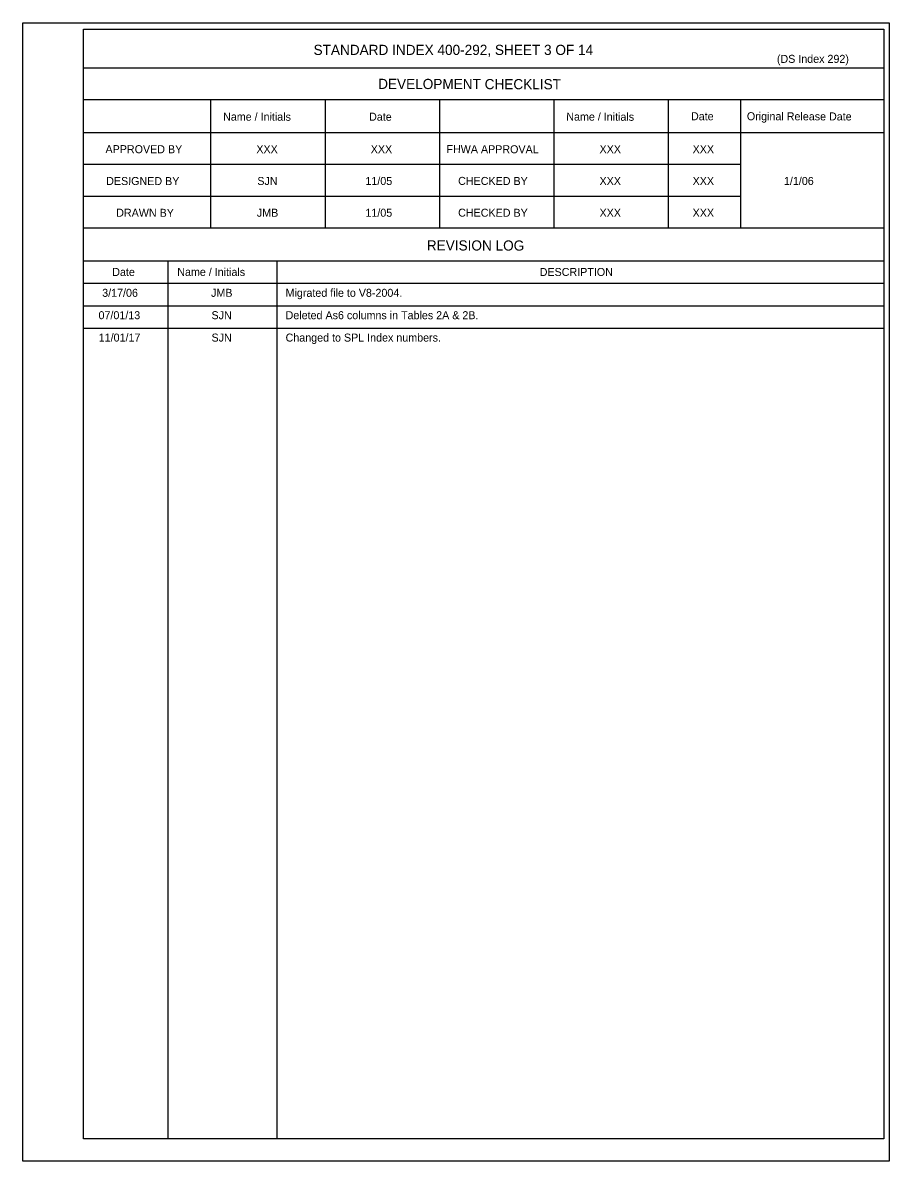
# Model space of a CAD drawing. Extents: x 10340.93 to 10343.14, y 76399.51 to 76400.59.
# Drawn here: x 10342.462 to 10343.144, y 76399.632 to 76400.528 of the extents above; entities that cross this region are included whole.
import ezdxf

# ---------------------------------------------------------------- set-up
doc = ezdxf.new("R2010")
doc.units = 0
doc.layers.add('AdhocPoint_dp', color=7, linetype='Continuous')
doc.layers.add('Border', color=7, linetype='Continuous')

msp = doc.modelspace()

# ---------------------------------------------------------------- linework, layer by layer
at = {"layer": 'AdhocPoint_dp'}
for p, q in [((10342.50988, 76400.30505), (10343.13946, 76400.30505)), ((10342.50988, 76400.28743), (10343.13946, 76400.28743))]:
    msp.add_line(p, q, dxfattribs=at)
at = {"layer": 'Border'}
for p, q in [((10343.13946, 76400.49202), (10342.50988, 76400.49202)), ((10343.13946, 76400.46702), (10342.50988, 76400.46702)), ((10342.60987, 76400.46702), (10342.60987, 76400.36615)), ((10342.69987, 76400.46702), (10342.69987, 76400.36615)), ((10342.78987, 76400.46702), (10342.78987, 76400.36615)), ((10342.87987, 76400.46702), (10342.87987, 76400.36615)), ((10342.96987, 76400.46702), (10342.96987, 76400.36615)), ((10343.02659, 76400.46702), (10343.02659, 76400.36615)), ((10343.13946, 76400.44115), (10342.50988, 76400.44115)), ((10343.02659, 76400.41615), (10342.50988, 76400.41615)), ((10343.02659, 76400.39115), (10342.50988, 76400.39115)), ((10343.13946, 76400.36615), (10342.50988, 76400.36615)), ((10343.13946, 76400.34028), (10342.50988, 76400.34028)), ((10342.57613, 76400.34028), (10342.57613, 76399.64945)), ((10342.66183, 76400.34028), (10342.66183, 76399.64945)), ((10343.13946, 76400.32266), (10342.50988, 76400.32266)), ((10342.46205, 76399.63191), (10342.46205, 76399.63191))]:
    msp.add_line(p, q, dxfattribs=at)
for points in [[(10342.46205, 76400.52774), (10343.14371, 76400.52774), (10343.14371, 76399.63191), (10342.46205, 76399.63191)], [(10342.50988, 76400.52266), (10343.13946, 76400.52266), (10343.13946, 76399.64945), (10342.50988, 76399.64945)]]:
    msp.add_lwpolyline(points, close=True, dxfattribs=at)

# ---------------------------------------------------------------- texts
at = {"layer": 'AdhocPoint_dp'}
for s, height, p in [('STANDARD INDEX 400-292, SHEET 3 OF 14', 0.008, (10342.69081, 76400.50241)), ('(DS Index 292)', 0.0063, (10343.05534, 76400.4962)), ('XXX', 0.0063, (10342.64581, 76400.42511)), ('XXX', 0.0063, (10342.73581, 76400.42511)), ('XXX', 0.0063, (10342.91581, 76400.42511)), ('XXX', 0.0063, (10342.98904, 76400.42511)), ('SJN', 0.0063, (10342.64658, 76400.40011)), ('11/05', 0.0063, (10342.73163, 76400.40011)), ('XXX', 0.0063, (10342.91581, 76400.40011)), ('XXX', 0.0063, (10342.98904, 76400.40011)), ('1/1/06', 0.0063, (10343.06089, 76400.40011)), ('JMB', 0.0063, (10342.64622, 76400.37511)), ('11/05', 0.0063, (10342.73163, 76400.37511)), ('XXX', 0.0063, (10342.91581, 76400.37511)), ('XXX', 0.0063, (10342.98904, 76400.37511)), ('DESCRIPTION', 0.0063, (10342.86874, 76400.3285)), ('3/17/06', 0.0063, (10342.52454, 76400.3121)), ('JMB', 0.0063, (10342.61018, 76400.3121)), ('Migrated file to V8-2004.', 0.0063, (10342.66882, 76400.3121)), ('07/01/13', 0.0063, (10342.52164, 76400.29448)), ('SJN', 0.0063, (10342.61054, 76400.29448)), ('Deleted As6 columns in Tables 2A & 2B.', 0.0063, (10342.66882, 76400.29448)), ('11/01/17', 0.0063, (10342.52179, 76400.27687)), ('SJN', 0.0063, (10342.61054, 76400.27687)), ('Changed to SPL Index numbers.', 0.0063, (10342.66882, 76400.27687))]:
    msp.add_text(s, height=height, dxfattribs=at).set_placement(p)
for s, height, p in [('DEVELOPMENT CHECKLIST', 0.008, (10342.74162, 76400.47567)), ('Name / Initials', 0.0063, (10342.61964, 76400.45074)), ('Date', 0.0063, (10342.73448, 76400.45069)), ('Name / Initials', 0.0063, (10342.88964, 76400.45074)), ('Date', 0.0063, (10342.98776, 76400.45105)), ('Original Release Date', 0.0063, (10343.03171, 76400.45105)), ('APPROVED BY', 0.0063, (10342.52712, 76400.42517)), ('FHWA APPROVAL', 0.0063, (10342.79535, 76400.42517)), ('DESIGNED BY', 0.0063, (10342.52765, 76400.40012)), ('CHECKED BY', 0.0063, (10342.80456, 76400.40017)), ('DRAWN BY', 0.0063, (10342.53555, 76400.37512)), ('CHECKED BY', 0.0063, (10342.80456, 76400.37517)), ('REVISION LOG', 0.008, (10342.77991, 76400.34861)), ('Date', 0.0063, (10342.53245, 76400.32852)), ('Name / Initials', 0.0063, (10342.58359, 76400.32857))]:
    msp.add_text(s, height=height, rotation=359.87563, dxfattribs=at).set_placement(p)

doc.saveas('drawing.dxf')
